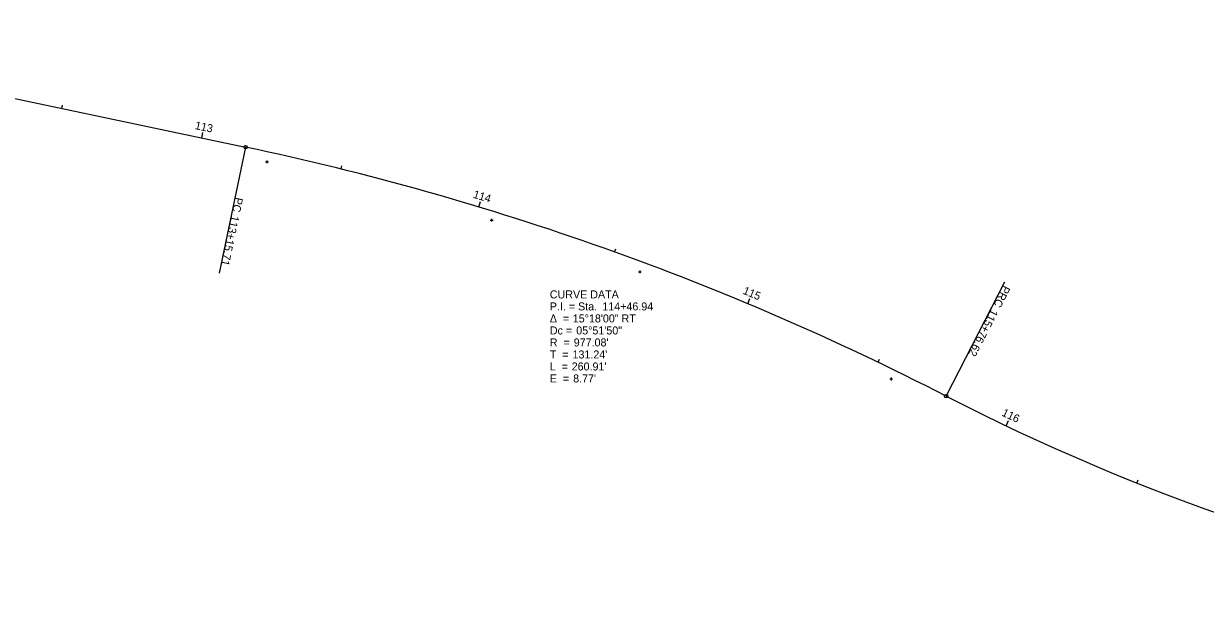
# Model space of a CAD drawing. Extents: x 2003596 to 2006888, y 572582 to 572983.
# Drawn here: x 2004009.3 to 2004422.8, y 572724.5 to 572927.3 of the extents above; entities that cross this region are included whole.
import ezdxf

# ---------------------------------------------------------------- set-up
doc = ezdxf.new("R2010")
doc.units = 0
for name, color, linetype in [('DR_X_Ditch', 7, 'Continuous'), ('DR_X_Erosion_Control', 7, 'Continuous'), ('DR_X_Headwall', 7, 'Continuous'), ('PM_X_Surveyed_Line', 7, 'Continuous'), ('PV_X_COP', 7, 'Continuous'), ('PV_X_Driveway', 7, 'Continuous'), ('RD_X_Fence', 7, 'Continuous'), ('SV_X_Top_of_Bank', 7, 'Continuous'), ('UT_X_Water_Cells', 7, 'Continuous'), ('VG_X_Cells', 7, 'Continuous'), ('VG_X_Tree_Line_Lt', 7, 'Continuous')]:
    doc.layers.add(name, color=color, linetype=linetype)

msp = doc.modelspace()

# ---------------------------------------------------------------- linework, layer by layer
at = {"layer": 'DR_X_Ditch'}
for p, q in [((2004022.66, 572897.61), (2004022.91, 572898.79)), ((2004071.58, 572887.3), (2004072, 572889.25)), ((2004120.38, 572876.39), (2004120.67, 572877.56)), ((2004168.58, 572863.13), (2004169.16, 572865.04)), ((2004216.04, 572847.42), (2004216.45, 572848.55)), ((2004262.64, 572829.3), (2004263.41, 572831.14)), ((2004308.25, 572808.82), (2004308.77, 572809.9)), ((2004353.04, 572786.6), (2004353.9, 572788.41)), ((2004398.85, 572766.59), (2004399.29, 572767.7))]:
    msp.add_line(p, q, dxfattribs=at)
at = {"layer": 'PM_X_Surveyed_Line'}
msp.add_line((2003882.01, 572927.27), (2004086.95, 572884.06), dxfattribs=at)
for centre, radius, start, end in [((2003885.35, 571928), 977.08, 62.79264, 78.09264), ((2004683.7, 573480.96), 769.07, 242.79359, 259.61026)]:
    msp.add_arc(centre, radius, start, end, dxfattribs=at)
at = {"layer": 'PV_X_COP'}
for p, q in [((2004086.95, 572884.06), (2004077.67, 572840.02)), ((2004332.08, 572796.97), (2004352.66, 572837))]:
    msp.add_line(p, q, dxfattribs=at)
for centre in [(2004086.95, 572884.06), (2004332.08, 572796.97)]:
    msp.add_circle(centre, 0.6, dxfattribs=at)
at = {"layer": 'RD_X_Fence'}
for p, q in [((2004071.58, 572887.3), (2004071.83, 572888.47)), ((2004168.58, 572863.13), (2004168.93, 572864.28)), ((2004262.64, 572829.3), (2004263.41, 572831.14)), ((2004353.04, 572786.6), (2004353.55, 572787.69))]:
    msp.add_line(p, q, dxfattribs=at)
at = {"layer": 'SV_X_Top_of_Bank'}
for p, q in [((2004086.95, 572884.06), (2004077.67, 572840.02)), ((2004332.08, 572796.97), (2004352.66, 572837))]:
    msp.add_line(p, q, dxfattribs=at)
for centre in [(2004086.95, 572884.06), (2004332.08, 572796.97)]:
    msp.add_circle(centre, 0.6, dxfattribs=at)
at = {"layer": 'UT_X_Water_Cells'}
msp.add_line((2004262.64, 572829.3), (2004263.1, 572830.41), dxfattribs=at)
at = {"layer": 'VG_X_Cells'}
for p, q in [((2004093.93, 572878.92), (2004094.93, 572878.92)), ((2004094.43, 572879.42), (2004094.43, 572878.42)), ((2004094.43, 572878.92), (2004094.43, 572878.92)), ((2004173.02, 572859.03), (2004173.02, 572858.03)), ((2004172.52, 572858.53), (2004173.52, 572858.53)), ((2004173.02, 572858.53), (2004173.02, 572858.53)), ((2004224.38, 572840.48), (2004225.38, 572840.48)), ((2004224.88, 572840.98), (2004224.88, 572839.98)), ((2004224.88, 572840.48), (2004224.88, 572840.48)), ((2004312.33, 572802.99), (2004313.33, 572802.99)), ((2004312.83, 572803.49), (2004312.83, 572802.49)), ((2004312.83, 572802.99), (2004312.83, 572802.99))]:
    msp.add_line(p, q, dxfattribs=at)
at = {"layer": 'VG_X_Tree_Line_Lt'}
for p, q in [((2004086.95, 572884.06), (2004077.67, 572840.02)), ((2004332.08, 572796.97), (2004352.66, 572837))]:
    msp.add_line(p, q, dxfattribs=at)
for centre in [(2004086.95, 572884.06), (2004332.08, 572796.97)]:
    msp.add_circle(centre, 0.6, dxfattribs=at)

# ---------------------------------------------------------------- texts
at = {"layer": 'DR_X_Ditch'}
for s, rotation, p in [('113', 348.0925, (2004069.06, 572890.43)), ('114', 343.1496, (2004166.34, 572866.42)), ('115', 337.2856, (2004260.72, 572832.86)), ('116', 334.5354, (2004351.3, 572790.25))]:
    msp.add_text(s, height=2.8, rotation=rotation, dxfattribs=at).set_placement(p)
at = {"layer": 'DR_X_Erosion_Control'}
for s, p in [('CURVE DATA', (2004193.4, 572831.16)), ('P.I. = Sta. ', (2004193.4, 572826.96)), ('114+46.94', (2004211.77, 572826.96)), ('Δ  = ', (2004193.4, 572822.76)), ('15°18\'00" RT', (2004201.43, 572822.76)), ('Dc = ', (2004193.4, 572818.56)), ('05°51\'50"', (2004202.64, 572818.56)), ('R  = ', (2004193.4, 572814.36)), ("977.08'", (2004201.77, 572814.36)), ('T  = ', (2004193.4, 572810.16)), ("131.24'", (2004201.34, 572810.16)), ('L  = ', (2004193.4, 572805.96)), ("260.91'", (2004201.05, 572805.96)), ('E  = ', (2004193.4, 572801.76)), ("8.77'", (2004201.56, 572801.76))]:
    msp.add_text(s, height=2.8, dxfattribs=at).set_placement(p)
at = {"layer": 'DR_X_Headwall'}
for s, p in [('CURVE DATA', (2004193.4, 572831.16)), ('P.I. = Sta. ', (2004193.4, 572826.96)), ('114+46.94', (2004211.77, 572826.96)), ('Δ  = ', (2004193.4, 572822.76)), ('15°18\'00" RT', (2004201.43, 572822.76)), ('Dc = ', (2004193.4, 572818.56)), ('05°51\'50"', (2004202.64, 572818.56)), ('R  = ', (2004193.4, 572814.36)), ("977.08'", (2004201.77, 572814.36)), ('T  = ', (2004193.4, 572810.16)), ("131.24'", (2004201.34, 572810.16)), ('L  = ', (2004193.4, 572805.96)), ("260.91'", (2004201.05, 572805.96)), ('E  = ', (2004193.4, 572801.76)), ("8.77'", (2004201.56, 572801.76))]:
    msp.add_text(s, height=2.8, dxfattribs=at).set_placement(p)
at = {"layer": 'PV_X_COP'}
for s, rotation, p in [('PC', 258.0926, (2004083.34, 572866.69)), ('113+15.71', 258.0926, (2004081.99, 572860.31)), ('PRC', 242.7936, (2004352.17, 572835.94)), ('115+76.62', 242.7936, (2004347.89, 572827.63))]:
    msp.add_text(s, height=2.8, rotation=rotation, dxfattribs=at).set_placement(p)
at = {"layer": 'PV_X_Driveway'}
for s, p in [('CURVE DATA', (2004193.4, 572831.16)), ('P.I. = Sta. ', (2004193.4, 572826.96)), ('114+46.94', (2004211.77, 572826.96)), ('Δ  = ', (2004193.4, 572822.76)), ('15°18\'00" RT', (2004201.43, 572822.76)), ('Dc = ', (2004193.4, 572818.56)), ('05°51\'50"', (2004202.64, 572818.56)), ('R  = ', (2004193.4, 572814.36)), ("977.08'", (2004201.77, 572814.36)), ('T  = ', (2004193.4, 572810.16)), ("131.24'", (2004201.34, 572810.16)), ('L  = ', (2004193.4, 572805.96)), ("260.91'", (2004201.05, 572805.96)), ('E  = ', (2004193.4, 572801.76)), ("8.77'", (2004201.56, 572801.76))]:
    msp.add_text(s, height=2.8, dxfattribs=at).set_placement(p)
at = {"layer": 'RD_X_Fence'}
msp.add_text('115', height=2.8, rotation=337.2856, dxfattribs=at).set_placement((2004260.72, 572832.86))
at = {"layer": 'SV_X_Top_of_Bank'}
for s, rotation, p in [('PC', 258.0926, (2004083.34, 572866.69)), ('113+15.71', 258.0926, (2004081.99, 572860.31)), ('PRC', 242.7936, (2004352.17, 572835.94)), ('115+76.62', 242.7936, (2004347.89, 572827.63))]:
    msp.add_text(s, height=2.8, rotation=rotation, dxfattribs=at).set_placement(p)
at = {"layer": 'VG_X_Tree_Line_Lt'}
for s, rotation, p in [('PC', 258.0926, (2004083.34, 572866.69)), ('113+15.71', 258.0926, (2004081.99, 572860.31)), ('PRC', 242.7936, (2004352.17, 572835.94)), ('115+76.62', 242.7936, (2004347.89, 572827.63))]:
    msp.add_text(s, height=2.8, rotation=rotation, dxfattribs=at).set_placement(p)

doc.saveas('drawing.dxf')
